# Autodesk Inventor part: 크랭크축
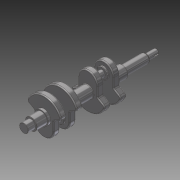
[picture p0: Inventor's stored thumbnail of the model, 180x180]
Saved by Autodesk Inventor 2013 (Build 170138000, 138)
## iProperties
Created: 2017-03
Part Number: 크랭크축
Material: 강철, 탄소
Document SubType Name: Modeling
Designer: mduedu
Density: 7.87 g/cm^3
Mass: 1576.89 g
Surface Area: 429.128 cm^2
Volume: 200.367 cm^3
Author: mduedu
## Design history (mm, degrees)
sketch "스케치1" dims "d5" = 50
  geometry: L1 (-19, 16.248)-(-19, -1.752); L2 (-19, -1.752)-(-33.503, -10.125); L3 (19, 16.248)-(19, -1.752); L4 (0, 16.248)-(0, -35); L5 (19, -1.752)-(33.503, -10.125); C1 r 8.5 at (0, 0); C2 r 13.5 at (0, 0); A1 r 35 centre (0, 0) between (-33.503, -10.125) and (0, -35); A2 r 35 centre (0, 0) between (0, -35) and (33.503, -10.125); A3 r 19 centre (0, 16.248) between (19, 16.248) and (0, 35.248); A4 r 19 centre (0, 16.248) between (0, 35.248) and (-19, 16.248); 3 further points
  constraints: 10 end point, 8 point on circle, 6 centre point, 5 coincident, 3 symmetric about line, 2 point on line, 1 parallel, 1 tangent, 1 vertical, 1 vertical alignment, 5 other
  dimensions: "d0" = 17 diameter of C1; "d1" = 27 diameter of C2; "d2" = 18 distance of L1.start L1.end; "d3" = 120 deg angle of L2 L1; "d4" = 35 radius of A1; "d6" = 19 radius of A4
extrude "돌출1" new body sketch "스케치1" distance "d7" = 12; taper "d8" = 0 deg
extrude "돌출2" join sketch "스케치1" distance "d9" = 5; taper "d10" = 0 deg
extrude "돌출3" join sketch "스케치1" distance "d11" = 90; taper "d12" = 0 deg
sketch "스케치2"
  geometry: C1 r 11 at (0, 16.248); C2 r 6 at (0, 16.248); A1 r 19 centre (0, 16.248) between (19, 16.248) and (-19, 16.248) reference; 1 further point
  constraints: 2 centre point, 2 coincident
  dimensions: "d13" = 22 diameter of C1; "d14" = 12 diameter of C2
extrude "돌출4" join sketch "스케치2" distance "d15" = 3; taper "d16" = 0 deg
extrude "돌출5" join sketch "스케치2" distance "d17" = 16; taper "d18" = 0 deg
fillet "모깎기1" dims "d19" = 3, "d20" = 5
fillet "모깎기2" dims "d21" = 2
sketch "스케치3"
  geometry: C1 r 11.5 at (0, 0); 1 further point
  constraints: 1 centre point, 1 coincident
  dimensions: "d22" = 23 diameter of C1
extrude "돌출6" join sketch "스케치3" distance "d23" = 19; taper "d24" = 0 deg
sketch "스케치4"
  geometry: C1 r 8.5 at (0, 0) reference; C2 r 5.5 at (0, 0); 1 further point
  constraints: 1 centre point
  dimensions: "d25" = 3 radial gap between concentric circles of C1 C2
extrude "돌출7" cut sketch "스케치4" distance "d26" = 20; taper "d27" = 0 deg
node "작업 평면1"
sketch "스케치5"
  geometry: L1 (-5.5, 0)-(5.5, 0) reference; L2 (-1.5, 0)-(1.5, 0); L3 (1.5, 0)-(1.5, 8.5); L4 (-1.5, 8.5)-(-1.5, 0); A1 r 1.5 centre (0, 8.5) between (1.5, 8.5) and (-1.5, 8.5); 1 further point
  constraints: 6 end point, 2 point on circle, 2 tangent, 1 centre point, 1 horizontal, 1 parallel, 1 perpendicular, 1 point on line, 1 vertical alignment
  dimensions: "d28" = 3 distance between parallel lines of L3 L4; "d30" = 10 dimension on A1 L1
extrude "돌출8" cut sketch "스케치5" distance "d31" = 1.8; taper "d32" = 0 deg
chamfer "모따기1" distance "d33" = 0.5; stored, may be unused: second distance "d34" = 2, angle "d35" = 45 deg
chamfer "모따기2" distance "d36" = 1; stored, may be unused: second distance "d37" = 2, angle "d38" = 45 deg
node "작업 평면2"
sketch "스케치6"
  geometry: C1 r 11.5 at (0, 0) reference; C2 r 11.5 at (0, 0) reference; 1 further point
extrude "돌출9" join sketch "스케치6" distance "d39" = 42; taper "d40" = 0 deg
sketch "스케치7" dims "d46" = 50
  geometry: L1 (-19, -16.248)-(-19, 1.752); L2 (19, -16.248)-(19, 1.752); L3 (-19, 1.752)-(-33.503, 10.125); L4 (19, 1.752)-(33.503, 10.125); L5 (0, -16.248)-(0, 35); C1 r 13.5 at (0, 0); C2 r 6 at (0, 0); A1 r 19 centre (0, -16.248) between (0, -35.248) and (19, -16.248); A2 r 19 centre (0, -16.248) between (-19, -16.248) and (0, -35.248); A3 r 35 centre (0, 0) between (0, 35) and (-33.503, 10.125); A4 r 35 centre (0, 0) between (33.503, 10.125) and (0, 35); 3 further points
  constraints: 10 end point, 8 point on circle, 6 centre point, 5 coincident, 3 symmetric about line, 2 point on line, 1 parallel, 1 tangent, 1 vertical, 5 other
  dimensions: "d41" = 12 diameter of C2; "d42" = 27 diameter of C1; "d43" = 18 distance of L2.start L2.end; "d44" = 120 deg angle of L4 L2; "d45" = 35 radius of A4; "d47" = 19 radius of A1
extrude "돌출10" join sketch "스케치7" distance "d48" = 12; taper "d49" = 0 deg
sketch "스케치8"
  geometry: C1 r 11 at (0, -16.248); C2 r 6 at (0, -16.248); A1 r 19 centre (0, -16.248) between (-19, -16.248) and (19, -16.248) reference; 1 further point
  constraints: 2 centre point, 2 coincident
  dimensions: "d50" = 22 diameter of C1; "d51" = 12 diameter of C2
extrude "돌출11" join sketch "스케치8" distance "d52" = 3; taper "d53" = 0 deg
extrude "돌출12" join sketch "스케치8" distance "d54" = 16; taper "d55" = 0 deg
fillet "모깎기3" dims "d56" = 3, "d57" = 5
fillet "모깎기4" dims "d58" = 2
chamfer "모따기3" distance "d59" = 1; stored, may be unused: second distance "d60" = 2, angle "d61" = 45 deg
node "작업 평면3"
fillet "모깎기5" dims "d62" = 1
sketch "스케치9"
  geometry: C1 r 13.5 at (0, 0) reference; 1 further point
extrude "돌출13" join sketch "스케치9" distance "d63" = 5; taper "d64" = 0 deg
sketch "스케치10"
  geometry: C1 r 8.5 at (0, 0) reference; C2 r 8.5 at (0, 0) reference; 1 further point
  dimensions: "d79" = 17 diameter of C1 (derived)
extrude "돌출14" join sketch "스케치10" distance "d65" = 34; taper "d66" = 0 deg
sketch "스케치11"
  geometry: C1 r 11.5 at (0, 0); 1 further point
  constraints: 1 centre point, 1 coincident
  dimensions: "d67" = 23 diameter of C1
extrude "돌출15" join sketch "스케치11" distance "d68" = 20; taper "d69" = 0 deg
chamfer "모따기4" distance "d70" = 0.5; stored, may be unused: second distance "d71" = 2, angle "d72" = 45 deg
sketch "스케치12"
  geometry: L1 (8.5, -70)-(-8.5, -70) reference; L2 (-8.5, -24)-(-8.5, -70) reference; L3 (-7.45, -70)-(-8.5, -68.181); L4 (5, -90)-(-5, -90) reference; L5 (0, -90)-(0, -70); 3 further points
  constraints: 4 end point, 2 midpoint, 2 point on line
  dimensions: "d80" = 14.9 diameter of L3.start L5; "d81" = 30 deg angle of L2 L3
revolve "회전1" sketch "스케치12" stored, may be unused: angle "d82" = 90 deg
fillet "모깎기7" dims "d83" = 2, "d84" = 1
node "솔리드1"
mirror "대칭1"
mirror "대칭2"
node "투영된 루프1"
node "투영된 루프2"
